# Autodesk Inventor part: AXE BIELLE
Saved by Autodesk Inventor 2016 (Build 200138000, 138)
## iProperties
Created: 2013-10
Part Number: AXE BIELLE
Material: Générique
Document SubType Name: Modeling
Designer: Bruno
Density: 1 g/cm^3
Appearance: Par défaut
Author: Bruno
Sending System: SolidWorks 2013
Last Author: christophe
Last Saved: 2014-02-15
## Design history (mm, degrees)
feature "Chanfrein1"
node "Solide1"
